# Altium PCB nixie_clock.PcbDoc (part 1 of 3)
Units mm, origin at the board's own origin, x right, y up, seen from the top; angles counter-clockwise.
Board outline 295 x 120 mm, 2 copper layers (Top Layer, Bottom Layer), stack 0.325 mm thick; 320 components, 396 nets, 1330 pads, 452 vias.
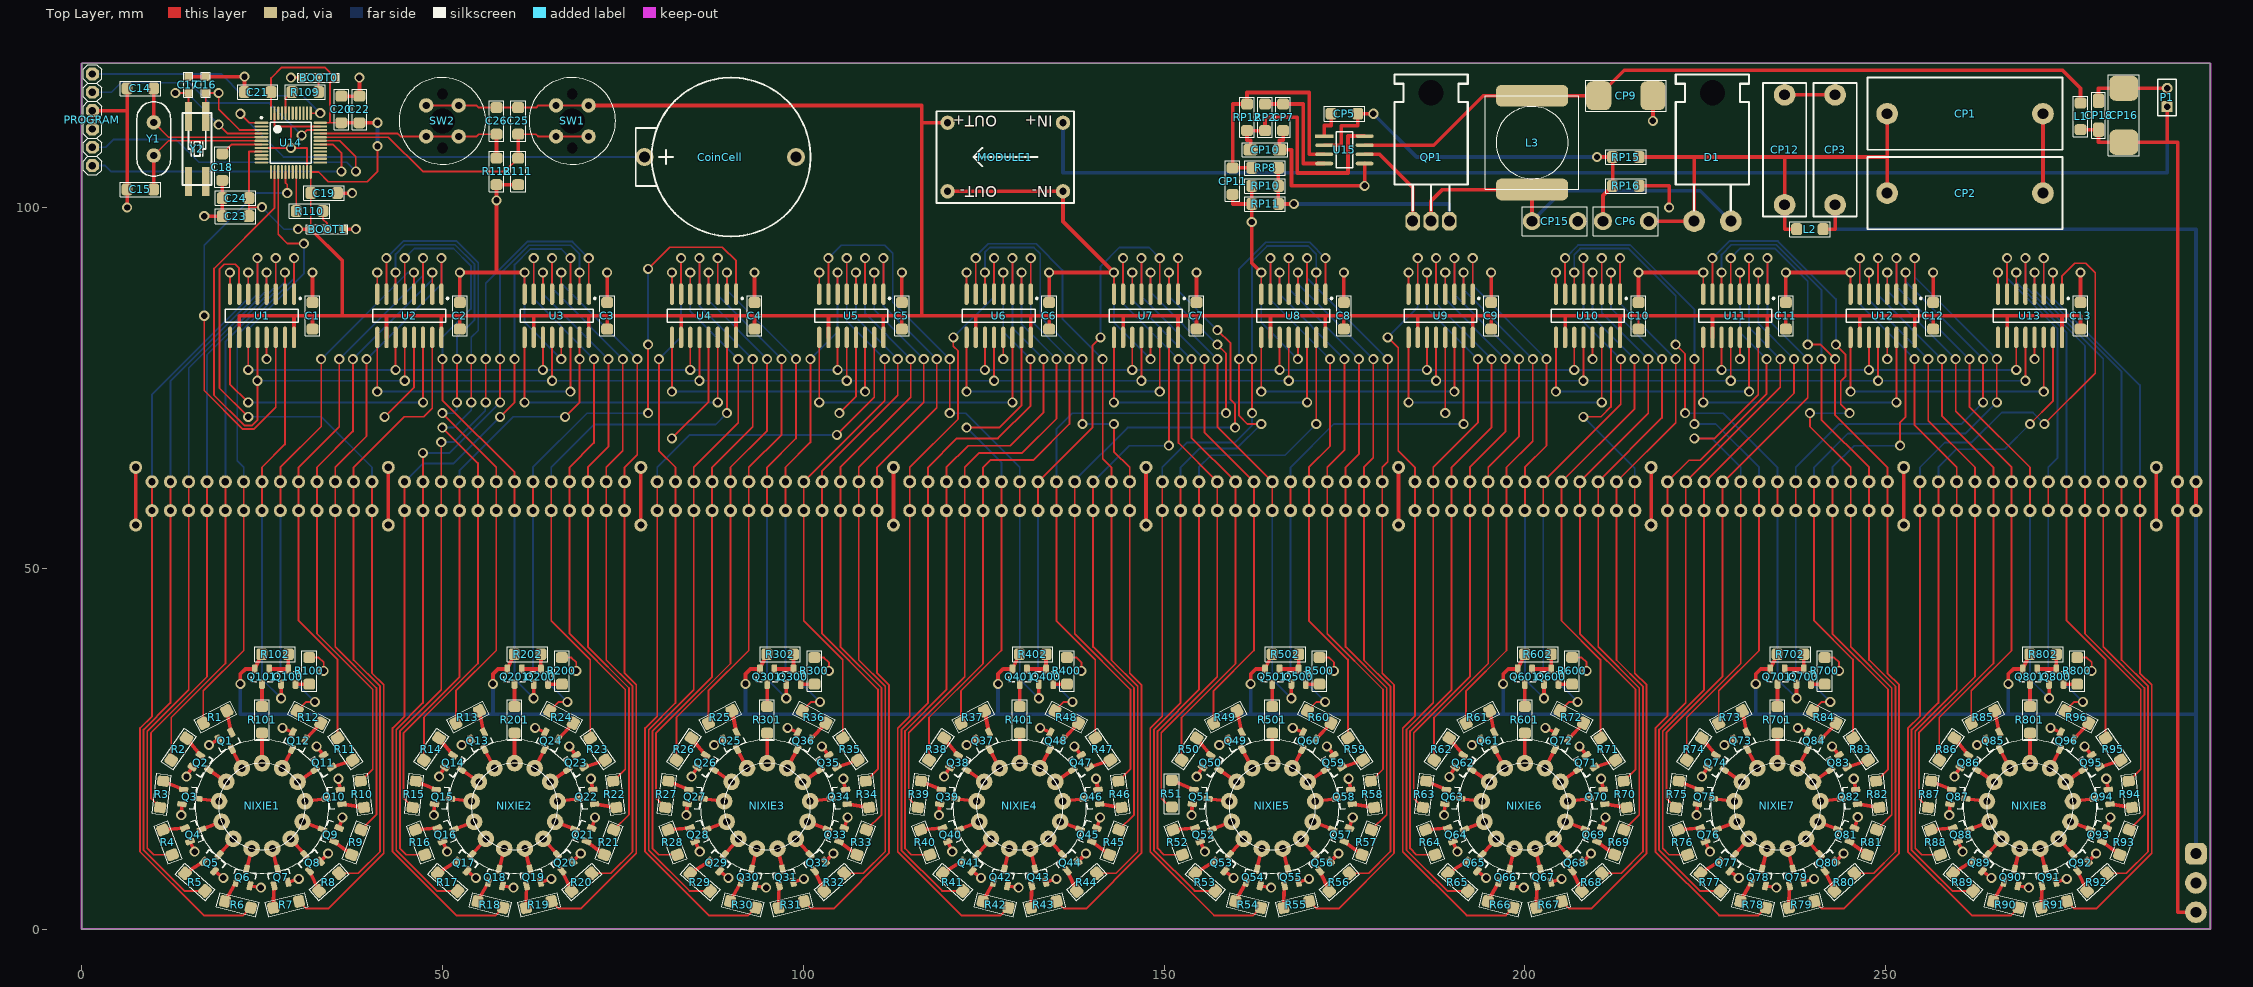
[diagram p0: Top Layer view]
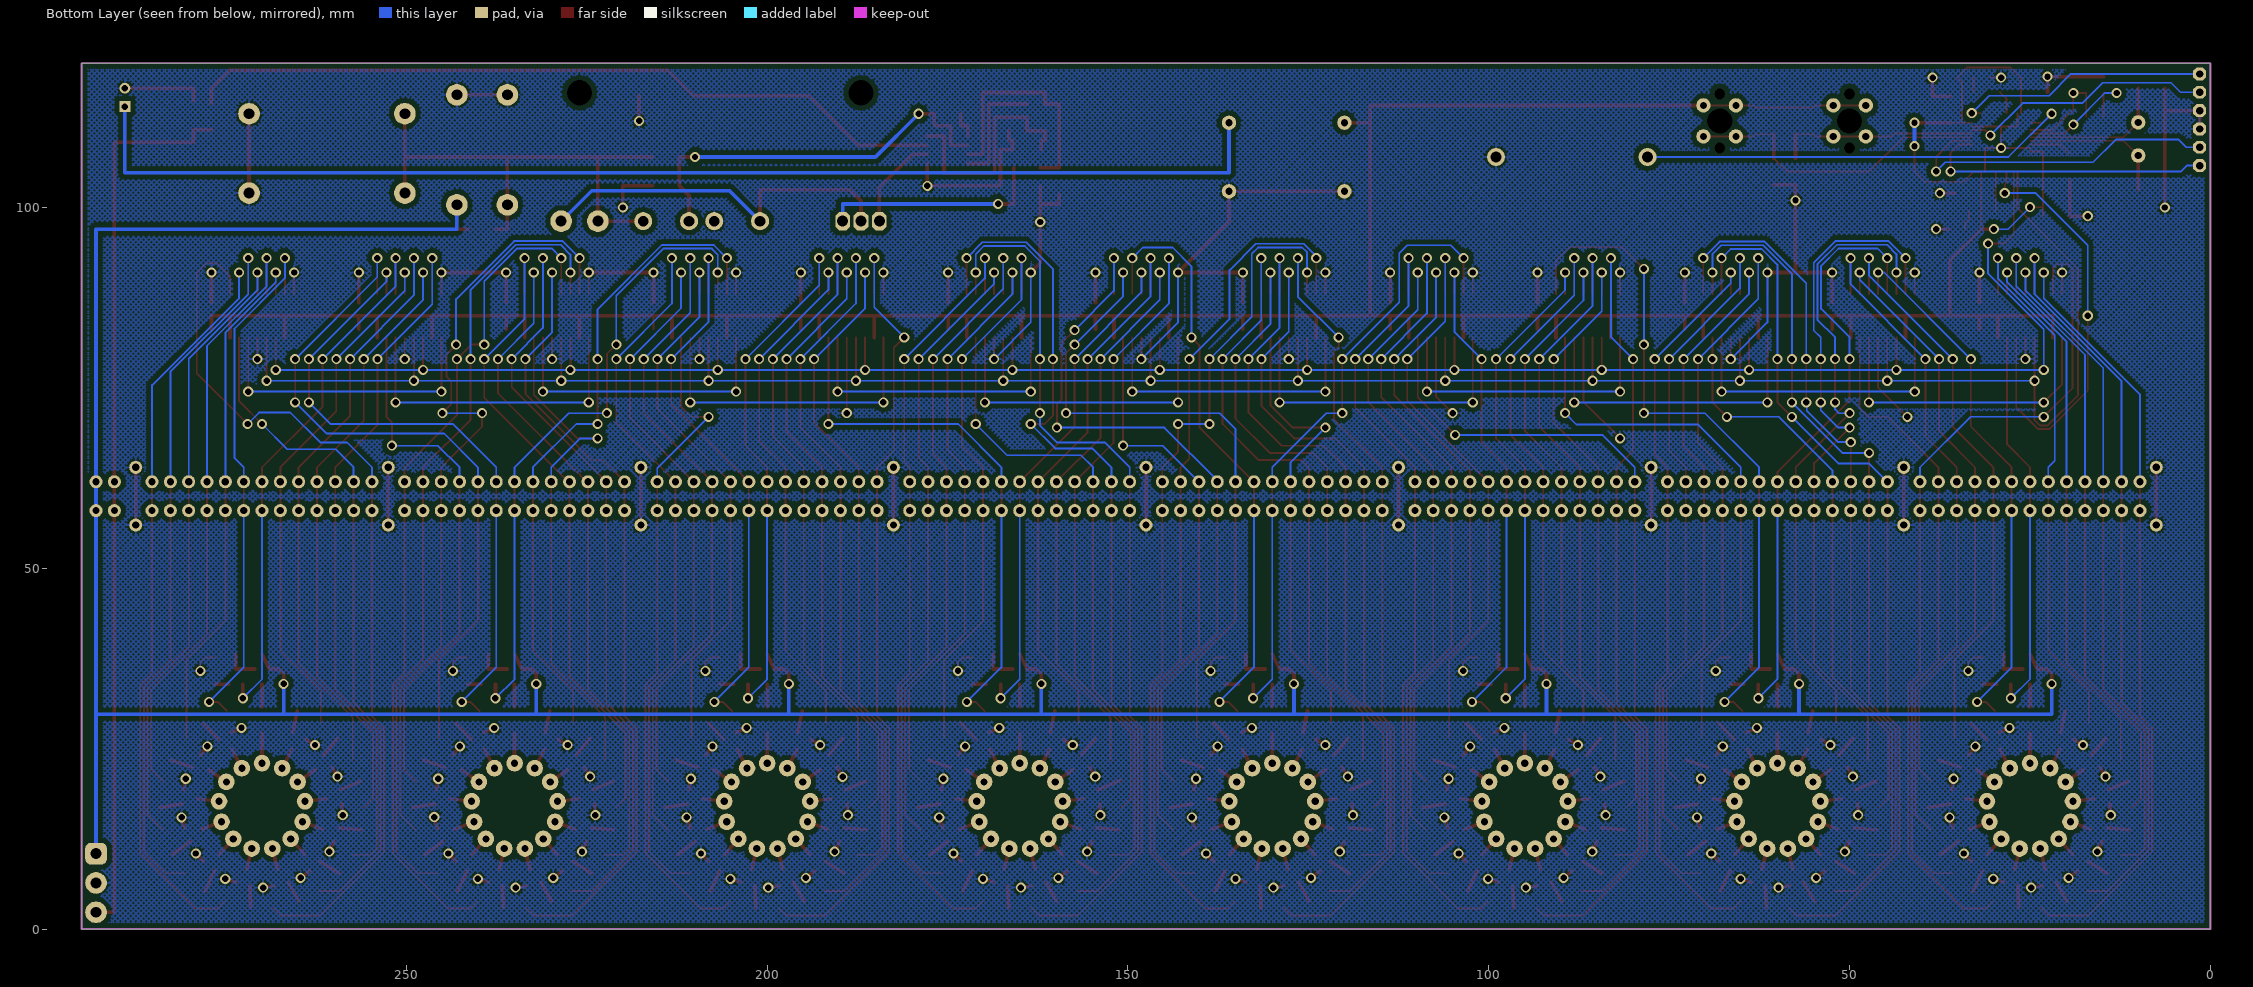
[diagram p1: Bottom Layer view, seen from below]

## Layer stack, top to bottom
Top Solder: solder mask 0.0102, Solder Resist, Dk 3.5
Top Layer: signal copper 0.0356
Dielectric 1: core 0.254, FR-4, Dk 4.2
Bottom Layer: signal copper 0.0356
Bottom Solder: solder mask 0.0102, Solder Resist, Dk 3.5

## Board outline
0,0 0,120 295,120 295,0

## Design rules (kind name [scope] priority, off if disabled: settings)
Clearance [All] p1: gap=0.635
PolygonConnect [All] p1: connectstyle=Relief reliefconductorwidth=0.254 reliefentries=4 polygonreliefangle="90 Angle" airgapwidth=0.254
RoutingVias [All] p1: holewidth=0.889 width=1.397 viastyle="Through Hole" minholewidth=0.889 minwidth=1.397 maxholewidth=0.889 maxwidth=1.397
SolderMaskExpansion [All] p1: expansion=0.102
Width [All] p1: maxlimit=0.508 minlimit=0.254 preferedwidth=0.508
30 further rules are at their usual default settings.

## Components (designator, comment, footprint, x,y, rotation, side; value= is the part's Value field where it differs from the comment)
BOOT0 "Header 3" SMDJ 33.97,118 r180 top
BOOT1 "Header 3" SMDJ 32.89,97 r0 top
C1 "CAP" SMD[1206] 32,85 r270 top
C2 "CAP" SMD[1206] 52.417,85 r270 top
C3 "CAP" SMD[1206] 72.833,85 r270 top
C4 "CAP" SMD[1206] 93.25,85 r270 top
C5 "CAP" SMD[1206] 113.667,85 r270 top
C6 "CAP" SMD[1206] 134.083,85 r270 top
C7 "CAP" SMD[1206] 154.5,85 r270 top
C8 "CAP" SMD[1206] 174.917,85 r270 top
C9 "CAP" SMD[1206] 195.333,85 r270 top
C10 "CAP" SMD[1206] 215.75,85 r270 top
C11 "CAP" SMD[1206] 236.167,85 r270 top
C12 "CAP" SMD[1206] 256.583,85 r270 top
C13 "CAP" SMD[1206] 277,85 r270 top
C14 "Cap" SMD[1206] 8.15,116.5 r0 top
C15 "Cap" SMD[1206] 8.15,102.5 r0 top
C16 "Cap" SMD[0805] 17.2,117 r270 top
C17 "Cap" SMD[0805] 14.8,117 r270 top
C18 "CAP" SMD[1206] 19.5,105.6 r90 top
C19 "CAP" SMD[1206] 33.6,102 r180 top
C20 "CAP" SMD[1206] 36,113.59 r270 top
C21 "CAP" SMD[1206] 24.41,116 r0 top
C22 "CAP" SMD[1206] 38.5,113.59 r270 top
C23 "CAP" SMD[1206] 21.34,98.8 r0 top
C24 "CAP" SMD[1206] 21.34,101.3 r0 top
C25 "CAP" SMD[1206] 60.5,112 r90 top
C26 "CAP" SMD[1206] 57.5,112 r90 top
CoinCell "Header 2" COINCELL[CR2032] 90,107 r180 top
CP1 "Cap Semi" MKT27X10 261,113 r0 top
CP2 "Cap Semi" MKT27X10 261,102 r0 top
CP3 "Cap Semi" MKT18X6 243,108 r90 top
CP5 "Cap Semi" SMD[1206] 175,113 r0 top
CP6 "Cap Semi" CAP[SEC] 214,98.11 r180 top
CP7 "Cap Semi" SMD[1206] 166.5,112.5 r270 top
CP9 "Cap Semi" SMDCAP[D] 214,115.5 r0 top
CP10 "Cap Semi" SMDCAP[A] 164,108 r0 top
CP11 "Cap Semi" SMD[1206] 159.5,103.66 r270 top
CP12 "Cap Semi" MKT18X6 236,108 r90 top
CP15 "Cap Semi" CAP[SEC] 204.16,98.11 r0 top
CP16 "Cap Semi" SMDCAP[D] 283,112.79 r90 top
CP18 "Cap Semi" SMDCAP[A] 279.5,112.79 r90 top
D1 "Diode" TO-220H-2PIN 226,107 r0 top
L1 "Inductor" SMD[1206] 277,112.63 r270 top
L2 "Inductor" SMD[1206] 239.5,97 r180 top
L3 "Inductor" POWERINDUCTOR 201,109 r90 top
MODULE1 "TINY_STEPDOWN" TINY_STEPDOWN 128,107 r180 top
NIXIE1 "IN14_NIXIE_TUBE" IN14_NIXIE_TUBE 25,17 r0 top
NIXIE2 "IN14_NIXIE_TUBE" IN14_NIXIE_TUBE 60,17 r0 top
NIXIE3 "IN14_NIXIE_TUBE" IN14_NIXIE_TUBE 95,17 r0 top
NIXIE4 "IN14_NIXIE_TUBE" IN14_NIXIE_TUBE 130,17 r0 top
NIXIE5 "IN14_NIXIE_TUBE" IN14_NIXIE_TUBE 165,17 r0 top
NIXIE6 "IN14_NIXIE_TUBE" IN14_NIXIE_TUBE 200,17 r0 top
NIXIE7 "IN14_NIXIE_TUBE" IN14_NIXIE_TUBE 235,17 r0 top
NIXIE8 "IN14_NIXIE_TUBE" IN14_NIXIE_TUBE 270,17 r0 top
P1 "Header 2" HDR1X2 289,114 r90 top
PROGRAM "Header 6" H1X06F 1.49,112.16 r270 top
Q1 "MMBTA42" SOT23(TO236) 20.353,25.855 r297.69 top
Q2 "MMBTA42" SOT23(TO236) 16.77,22.681 r325.38 top
Q3 "MMBTA42" SOT23(TO236) 15.073,18.206 r353.08 top
Q4 "MMBTA42" SOT23(TO236) 15.65,13.454 r20.77 top
Q5 "MMBTA42" SOT23(TO236) 18.369,9.515 r48.46 top
Q6 "MMBTA42" SOT23(TO236) 22.607,7.291 r76.15 top
Q7 "MMBTA42" SOT23(TO236) 27.393,7.29 r103.84 top
Q8 "MMBTA42" SOT23(TO236) 31.631,9.515 r131.54 top
Q9 "MMBTA42" SOT23(TO236) 34.35,13.453 r159.23 top
Q10 "MMBTA42" SOT23(TO236) 34.927,18.205 r186.92 top
Q11 "MMBTA42" SOT23(TO236) 33.23,22.68 r214.61 top
Q12 "MMBTA42" SOT23(TO236) 29.648,25.854 r242.3 top
Q13 "MMBTA42" SOT23(TO236) 55.353,25.855 r297.69 top
Q14 "MMBTA42" SOT23(TO236) 51.77,22.681 r325.38 top
Q15 "MMBTA42" SOT23(TO236) 50.073,18.206 r353.08 top
Q16 "MMBTA42" SOT23(TO236) 50.65,13.454 r20.77 top
Q17 "MMBTA42" SOT23(TO236) 53.369,9.515 r48.46 top
Q18 "MMBTA42" SOT23(TO236) 57.607,7.291 r76.15 top
Q19 "MMBTA42" SOT23(TO236) 62.393,7.29 r103.84 top
Q20 "MMBTA42" SOT23(TO236) 66.631,9.515 r131.54 top
Q21 "MMBTA42" SOT23(TO236) 69.35,13.453 r159.23 top
Q22 "MMBTA42" SOT23(TO236) 69.927,18.205 r186.92 top
Q23 "MMBTA42" SOT23(TO236) 68.23,22.68 r214.61 top
Q24 "MMBTA42" SOT23(TO236) 64.648,25.854 r242.3 top
Q25 "MMBTA42" SOT23(TO236) 90.353,25.855 r297.69 top
Q26 "MMBTA42" SOT23(TO236) 86.77,22.681 r325.38 top
Q27 "MMBTA42" SOT23(TO236) 85.073,18.206 r353.08 top
Q28 "MMBTA42" SOT23(TO236) 85.65,13.454 r20.77 top
Q29 "MMBTA42" SOT23(TO236) 88.369,9.515 r48.46 top
Q30 "MMBTA42" SOT23(TO236) 92.607,7.291 r76.15 top
Q31 "MMBTA42" SOT23(TO236) 97.393,7.29 r103.84 top
Q32 "MMBTA42" SOT23(TO236) 101.631,9.515 r131.54 top
Q33 "MMBTA42" SOT23(TO236) 104.35,13.453 r159.23 top
Q34 "MMBTA42" SOT23(TO236) 104.927,18.205 r186.92 top
Q35 "MMBTA42" SOT23(TO236) 103.23,22.68 r214.61 top
Q36 "MMBTA42" SOT23(TO236) 99.648,25.854 r242.3 top
Q37 "MMBTA42" SOT23(TO236) 125.353,25.855 r297.69 top
Q38 "MMBTA42" SOT23(TO236) 121.77,22.681 r325.38 top
Q39 "MMBTA42" SOT23(TO236) 120.073,18.206 r353.08 top
Q40 "MMBTA42" SOT23(TO236) 120.65,13.454 r20.77 top
Q41 "MMBTA42" SOT23(TO236) 123.369,9.515 r48.46 top
Q42 "MMBTA42" SOT23(TO236) 127.607,7.291 r76.15 top
Q43 "MMBTA42" SOT23(TO236) 132.393,7.29 r103.84 top
Q44 "MMBTA42" SOT23(TO236) 136.631,9.515 r131.54 top
Q45 "MMBTA42" SOT23(TO236) 139.35,13.453 r159.23 top
Q46 "MMBTA42" SOT23(TO236) 139.927,18.205 r186.92 top
Q47 "MMBTA42" SOT23(TO236) 138.23,22.68 r214.61 top
Q48 "MMBTA42" SOT23(TO236) 134.648,25.854 r242.3 top
Q49 "MMBTA42" SOT23(TO236) 160.353,25.855 r297.69 top
Q50 "MMBTA42" SOT23(TO236) 156.77,22.681 r325.38 top
Q51 "MMBTA42" SOT23(TO236) 155.073,18.206 r353.08 top
Q52 "MMBTA42" SOT23(TO236) 155.65,13.454 r20.77 top
Q53 "MMBTA42" SOT23(TO236) 158.369,9.515 r48.46 top
Q54 "MMBTA42" SOT23(TO236) 162.607,7.291 r76.15 top
Q55 "MMBTA42" SOT23(TO236) 167.393,7.29 r103.84 top
Q56 "MMBTA42" SOT23(TO236) 171.631,9.515 r131.54 top
Q57 "MMBTA42" SOT23(TO236) 174.35,13.453 r159.23 top
Q58 "MMBTA42" SOT23(TO236) 174.927,18.205 r186.92 top
Q59 "MMBTA42" SOT23(TO236) 173.23,22.68 r214.61 top
Q60 "MMBTA42" SOT23(TO236) 169.648,25.854 r242.3 top
Q61 "MMBTA42" SOT23(TO236) 195.353,25.855 r297.69 top
Q62 "MMBTA42" SOT23(TO236) 191.77,22.681 r325.38 top
Q63 "MMBTA42" SOT23(TO236) 190.073,18.206 r353.08 top
Q64 "MMBTA42" SOT23(TO236) 190.65,13.454 r20.77 top
Q65 "MMBTA42" SOT23(TO236) 193.369,9.515 r48.46 top
Q66 "MMBTA42" SOT23(TO236) 197.607,7.291 r76.15 top
Q67 "MMBTA42" SOT23(TO236) 202.393,7.29 r103.84 top
Q68 "MMBTA42" SOT23(TO236) 206.631,9.515 r131.54 top
Q69 "MMBTA42" SOT23(TO236) 209.35,13.453 r159.23 top
Q70 "MMBTA42" SOT23(TO236) 209.927,18.205 r186.92 top
Q71 "MMBTA42" SOT23(TO236) 208.23,22.68 r214.61 top
Q72 "MMBTA42" SOT23(TO236) 204.648,25.854 r242.3 top
Q73 "MMBTA42" SOT23(TO236) 230.353,25.855 r297.69 top
Q74 "MMBTA42" SOT23(TO236) 226.77,22.681 r325.38 top
Q75 "MMBTA42" SOT23(TO236) 225.073,18.206 r353.08 top
Q76 "MMBTA42" SOT23(TO236) 225.65,13.454 r20.77 top
Q77 "MMBTA42" SOT23(TO236) 228.369,9.515 r48.46 top
Q78 "MMBTA42" SOT23(TO236) 232.607,7.291 r76.15 top
Q79 "MMBTA42" SOT23(TO236) 237.393,7.29 r103.84 top
Q80 "MMBTA42" SOT23(TO236) 241.631,9.515 r131.54 top
Q81 "MMBTA42" SOT23(TO236) 244.35,13.453 r159.23 top
Q82 "MMBTA42" SOT23(TO236) 244.927,18.205 r186.92 top
Q83 "MMBTA42" SOT23(TO236) 243.23,22.68 r214.61 top
Q84 "MMBTA42" SOT23(TO236) 239.648,25.854 r242.3 top
Q85 "MMBTA42" SOT23(TO236) 265.353,25.855 r297.69 top
Q86 "MMBTA42" SOT23(TO236) 261.77,22.681 r325.38 top
Q87 "MMBTA42" SOT23(TO236) 260.073,18.206 r353.08 top
Q88 "MMBTA42" SOT23(TO236) 260.65,13.454 r20.77 top
Q89 "MMBTA42" SOT23(TO236) 263.369,9.515 r48.46 top
Q90 "MMBTA42" SOT23(TO236) 267.607,7.291 r76.15 top
Q91 "MMBTA42" SOT23(TO236) 272.393,7.29 r103.84 top
Q92 "MMBTA42" SOT23(TO236) 276.631,9.515 r131.54 top
Q93 "MMBTA42" SOT23(TO236) 279.35,13.453 r159.23 top
Q94 "MMBTA42" SOT23(TO236) 279.927,18.205 r186.92 top
Q95 "MMBTA42" SOT23(TO236) 278.23,22.68 r214.61 top
Q96 "MMBTA42" SOT23(TO236) 274.648,25.854 r242.3 top
Q100 "MMBTA42" SOT23(TO236) 28.65,35 r90 top
Q101 "MMBTA92" SOT23(TO236) 25,35 r270 top
Q200 "MMBTA42" SOT23(TO236) 63.65,35 r90 top
Q201 "MMBTA92" SOT23(TO236) 60,35 r270 top
Q300 "MMBTA42" SOT23(TO236) 98.65,35 r90 top
Q301 "MMBTA92" SOT23(TO236) 95,35 r270 top
Q400 "MMBTA42" SOT23(TO236) 133.65,35 r90 top
Q401 "MMBTA92" SOT23(TO236) 130,35 r270 top
Q500 "MMBTA42" SOT23(TO236) 168.65,35 r90 top
Q501 "MMBTA92" SOT23(TO236) 165,35 r270 top
Q600 "MMBTA42" SOT23(TO236) 203.65,35 r90 top
Q601 "MMBTA92" SOT23(TO236) 200,35 r270 top
Q700 "MMBTA42" SOT23(TO236) 238.65,35 r90 top
Q701 "MMBTA92" SOT23(TO236) 235,35 r270 top
Q800 "MMBTA42" SOT23(TO236) 273.65,35 r90 top
Q801 "MMBTA92" SOT23(TO236) 270,35 r270 top
QP1 "IRFB4229" TO-220H 187,107 r0 top
R1 "RES" SMD[1206] 18.494,29.396 r207.69 top
R2 "RES" SMD[1206] 13.478,24.953 r235.38 top
R3 "RES" SMD[1206] 11.102,18.688 r263.08 top
R4 "RES" SMD[1206] 11.91,12.036 r290.77 top
R5 "RES" SMD[1206] 15.716,6.521 r318.46 top
R6 "RES" SMD[1206] 21.649,3.407 r346.15 top
R7 "RES" SMD[1206] 28.35,3.407 r13.84 top
R8 "RES" SMD[1206] 34.283,6.52 r41.54 top
R9 "RES" SMD[1206] 38.09,12.035 r69.23 top
R10 "RES" SMD[1206] 38.898,18.687 r96.92 top
R11 "RES" SMD[1206] 36.522,24.952 r124.61 top
R12 "RES" SMD[1206] 31.507,29.396 r152.3 top
R13 "RES" SMD[1206] 53.494,29.396 r207.49 top
R14 "RES" SMD[1206] 48.478,24.953 r235.38 top
R15 "RES" SMD[1206] 46.102,18.688 r263.08 top
R16 "RES" SMD[1206] 46.91,12.036 r290.77 top
R17 "RES" SMD[1206] 50.716,6.521 r318.46 top
R18 "RES" SMD[1206] 56.649,3.407 r346.15 top
R19 "RES" SMD[1206] 63.35,3.407 r13.84 top
R20 "RES" SMD[1206] 69.283,6.52 r41.54 top
R21 "RES" SMD[1206] 73.09,12.035 r69.23 top
R22 "RES" SMD[1206] 73.898,18.687 r96.92 top
R23 "RES" SMD[1206] 71.522,24.952 r124.61 top
R24 "RES" SMD[1206] 66.507,29.396 r152.3 top
R25 "RES" SMD[1206] 88.494,29.396 r207.69 top
R26 "RES" SMD[1206] 83.478,24.953 r235.38 top
R27 "RES" SMD[1206] 81.102,18.688 r263.08 top
R28 "RES" SMD[1206] 81.91,12.036 r290.77 top
R29 "RES" SMD[1206] 85.716,6.521 r318.46 top
R30 "RES" SMD[1206] 91.649,3.407 r346.15 top
R31 "RES" SMD[1206] 98.35,3.407 r13.84 top
R32 "RES" SMD[1206] 104.283,6.52 r41.54 top
R33 "RES" SMD[1206] 108.09,12.035 r69.23 top
R34 "RES" SMD[1206] 108.898,18.687 r96.92 top
R35 "RES" SMD[1206] 106.522,24.952 r124.61 top
R36 "RES" SMD[1206] 101.507,29.396 r152.3 top
R37 "RES" SMD[1206] 123.494,29.396 r207.69 top
R38 "RES" SMD[1206] 118.478,24.953 r235.38 top
R39 "RES" SMD[1206] 116.102,18.688 r263.08 top
R40 "RES" SMD[1206] 116.91,12.036 r290.77 top
R41 "RES" SMD[1206] 120.716,6.521 r318.46 top
R42 "RES" SMD[1206] 126.649,3.407 r346.15 top
R43 "RES" SMD[1206] 133.35,3.407 r13.84 top
R44 "RES" SMD[1206] 139.283,6.52 r41.54 top
R45 "RES" SMD[1206] 143.09,12.035 r69.23 top
R46 "RES" SMD[1206] 143.898,18.687 r96.92 top
R47 "RES" SMD[1206] 141.522,24.952 r124.61 top
R48 "RES" SMD[1206] 136.507,29.396 r152.3 top
R49 "RES" SMD[1206] 158.494,29.396 r207.69 top
R50 "RES" SMD[1206] 153.478,24.953 r235.38 top
R51 "RES" SMD[1206] 151.075,18.775 r270 top
R52 "RES" SMD[1206] 151.91,12.036 r290.77 top
R53 "RES" SMD[1206] 155.716,6.521 r318.46 top
R54 "RES" SMD[1206] 161.649,3.407 r346.15 top
R55 "RES" SMD[1206] 168.35,3.407 r13.84 top
R56 "RES" SMD[1206] 174.283,6.52 r41.54 top
R57 "RES" SMD[1206] 178.09,12.035 r69.23 top
R58 "RES" SMD[1206] 178.898,18.687 r96.92 top
R59 "RES" SMD[1206] 176.522,24.952 r124.61 top
R60 "RES" SMD[1206] 171.507,29.396 r152.3 top
R61 "RES" SMD[1206] 193.494,29.396 r207.69 top
R62 "RES" SMD[1206] 188.478,24.953 r235.38 top
R63 "RES" SMD[1206] 186.102,18.688 r263.08 top
R64 "RES" SMD[1206] 186.91,12.036 r290.77 top
R65 "RES" SMD[1206] 190.716,6.521 r318.46 top
R66 "RES" SMD[1206] 196.649,3.407 r346.15 top
R67 "RES" SMD[1206] 203.35,3.407 r13.84 top
R68 "RES" SMD[1206] 209.283,6.52 r41.54 top
R69 "RES" SMD[1206] 213.09,12.035 r69.23 top
R70 "RES" SMD[1206] 213.898,18.687 r96.92 top
R71 "RES" SMD[1206] 211.522,24.952 r124.61 top
R72 "RES" SMD[1206] 206.507,29.396 r152.3 top
R73 "RES" SMD[1206] 228.494,29.396 r207.69 top
R74 "RES" SMD[1206] 223.478,24.953 r235.38 top
R75 "RES" SMD[1206] 221.102,18.688 r263.08 top
R76 "RES" SMD[1206] 221.91,12.036 r290.77 top
R77 "RES" SMD[1206] 225.716,6.521 r318.46 top
R78 "RES" SMD[1206] 231.649,3.407 r346.15 top
R79 "RES" SMD[1206] 238.35,3.407 r13.84 top
R80 "RES" SMD[1206] 244.283,6.52 r41.54 top
R81 "RES" SMD[1206] 248.09,12.035 r69.23 top
R82 "RES" SMD[1206] 248.898,18.687 r96.92 top
R83 "RES" SMD[1206] 246.522,24.952 r124.61 top
R84 "RES" SMD[1206] 241.507,29.396 r152.3 top
R85 "RES" SMD[1206] 263.494,29.396 r207.69 top
R86 "RES" SMD[1206] 258.478,24.953 r235.38 top
R87 "RES" SMD[1206] 256.102,18.688 r263.08 top
R88 "RES" SMD[1206] 256.91,12.036 r290.77 top
R89 "RES" SMD[1206] 260.716,6.521 r318.46 top
R90 "RES" SMD[1206] 266.649,3.407 r346.15 top
R91 "RES" SMD[1206] 273.35,3.407 r13.84 top
R92 "RES" SMD[1206] 279.283,6.52 r41.54 top
R93 "RES" SMD[1206] 283.09,12.035 r69.23 top
R94 "RES" SMD[1206] 283.898,18.687 r96.92 top
R95 "RES" SMD[1206] 281.522,24.952 r124.61 top
R96 "RES" SMD[1206] 276.507,29.396 r152.3 top
R100 "RES" SMD[1206] 31.55,35.795 r90 top
R101 "RES" SMD[1206] 25,29 r270 top
R102 "RES" SMD[1206] 26.81,38.1 r0 top
R109 "RES" SMD[1206] 31,116 r180 top
R110 "RES" SMD[1206] 31.59,99.5 r0 top
R111 "RES" SMD[1206] 60.5,105 r90 top
R112 "RES" SMD[1206] 57.5,105 r90 top
R200 "RES" SMD[1206] 66.55,35.795 r90 top
R201 "RES" SMD[1206] 60,29 r270 top
R202 "RES" SMD[1206] 61.81,38.1 r0 top
R300 "RES" SMD[1206] 101.55,35.795 r90 top
R301 "RES" SMD[1206] 95,29 r270 top
R302 "RES" SMD[1206] 96.81,38.1 r0 top
R400 "RES" SMD[1206] 136.55,35.795 r90 top
R401 "RES" SMD[1206] 130,29 r270 top
R402 "RES" SMD[1206] 131.81,38.1 r0 top
R500 "RES" SMD[1206] 171.55,35.795 r90 top
R501 "RES" SMD[1206] 165,29 r270 top
R502 "RES" SMD[1206] 166.81,38.1 r0 top
R600 "RES" SMD[1206] 206.55,35.795 r90 top
R601 "RES" SMD[1206] 200,29 r270 top
R602 "RES" SMD[1206] 201.81,38.1 r0 top
R700 "RES" SMD[1206] 241.55,35.795 r90 top
R701 "RES" SMD[1206] 235,29 r270 top
R702 "RES" SMD[1206] 236.81,38.1 r0 top
R800 "RES" SMD[1206] 276.55,35.795 r90 top
R801 "RES" SMD[1206] 270,29 r270 top
R802 "RES" SMD[1206] 271.81,38.1 r0 top
RP2 "Res2" SMD[1206] 164,112.5 r90 top
RP8 "Res2" SMD[1206] 164,105.5 r0 top
RP10 "Res2" SMD[1206] 164,103 r180 top
RP11 "Res2" SMD[1206] 164,100.5 r180 top
RP12 "Res2" SMD[1206] 161.5,112.5 r90 top
RP15 "Res2" SMD[1206] 214,107 r180 top
RP16 "Res2" SMD[1206] 214,103 r0 top
SW1 "SW-PB" PUSHBUTTON 68,112 r0 top
SW2 "SW-PB" PUSHBUTTON 50,112 r0 top
U1 "74HC595D" SOIC16 25,85 r270 top
U2 "74HC595D" SOIC16 45.417,85 r270 top
U3 "74HC595D" SOIC16 65.833,85 r270 top
U4 "74HC595D" SOIC16 86.25,85 r270 top
U5 "74HC595D" SOIC16 106.667,85 r270 top
U6 "74HC595D" SOIC16 127.083,85 r270 top
U7 "74HC595D" SOIC16 147.5,85 r270 top
U8 "74HC595D" SOIC16 167.917,85 r270 top
U9 "74HC595D" SOIC16 188.333,85 r270 top
U10 "74HC595D" SOIC16 208.75,85 r270 top
U11 "74HC595D" SOIC16 229.167,85 r270 top
U12 "74HC595D" SOIC16 249.583,85 r270 top
U13 "74HC595D" SOIC16 270,85 r270 top
U14 "STM32F130CBT6" LQFP48 29,109 r0 top
U15 "UCC3803" SOIC8 175,108 r0 top
Y1 "XTAL" CRYSTALL 10,109.5 r90 top
Y2 "XTAL" MC406[32.768KHZ] 16,108.12 r270 top

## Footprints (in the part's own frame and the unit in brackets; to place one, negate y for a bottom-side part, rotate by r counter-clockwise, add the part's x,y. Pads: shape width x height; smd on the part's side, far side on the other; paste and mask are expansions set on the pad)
CAP[SEC] [mm]
  round 2.5 hole 1.5: 1(-3.175,0) 2(3.175,0)
  silkscreen extent -4.5,-2 4.5,2
COINCELL[CR2032] [mm]
  round 2.5 hole 1.5: 1(-9,0) 2(12,0)
  silkscreen extent -11,-11 13.2,11
CRYSTALL [mm]
  round 2 hole 1: 1(-2.293,0) 2(2.293,0)
  silkscreen extent -5.16,-2.32 5.16,2.32
H1X06F [mil]
  oct 70x70 hole 40: 1(-250,0) 2(-150,0) 3(-50,0) 4(50,0) 5(150,0) 6(250,0)
  silkscreen extent -300,-50 300,50
HDR1X2 [mm] "Connector; Header; 2 Position"
  rect 1.5x1.5 hole 0.9: 1(0,0)
  round 1.5 hole 0.9: 2(2.54,0)
  silkscreen extent -1.27,-1.27 3.81,1.27
IN14_NIXIE_TUBE [mm]
  round 2.3 hole 1: 0(4.938,3.408) 1(-4.938,3.408) 2(-5.956,0.723) 3(-5.61,-2.128) 4(-3.979,-4.491) 5(-1.436,-5.826) 6(1.436,-5.826) 7(3.979,-4.491) 8(5.61,-2.128) 9(5.956,0.723) A(0,6) LP(-2.788,5.313) RP(2.789,5.313)
  silkscreen extent -9.25,-9.25 9.25,9.25
LQFP48 [mm] "TSQFP, 48-Leads, Body 9.0x9.0mm (max), Pitch 0.50mm, IPC Medium Density"
  oval 1.905x0.3 smd: 1(-4.075,2.75) 2(-4.075,2.25) 3(-4.075,1.75) 4(-4.075,1.25) 5(-4.075,0.75) 6(-4.075,0.25) 7(-4.075,-0.25) 8(-4.075,-0.75) 9(-4.075,-1.25) 10(-4.075,-1.75) 11(-4.075,-2.25) 12(-4.075,-2.75) 25(4.075,-2.75) 26(4.075,-2.25) 27(4.075,-1.75) 28(4.075,-1.25) 29(4.075,-0.75) 30(4.075,-0.25) 31(4.075,0.25) 32(4.075,0.75) 33(4.075,1.25) 34(4.075,1.75) 35(4.075,2.25) 36(4.075,2.75)
  oval 0.3x1.905 smd: 13(-2.75,-4.075) 14(-2.25,-4.075) 15(-1.75,-4.075) 16(-1.25,-4.075) 17(-0.75,-4.075) 18(-0.25,-4.075) 19(0.25,-4.075) 20(0.75,-4.075) 21(1.25,-4.075) 22(1.75,-4.075) 23(2.25,-4.075) 24(2.75,-4.075) 37(2.75,4.075) 38(2.25,4.075) 39(1.75,4.075) 40(1.25,4.075) 41(0.75,4.075) 42(0.25,4.075) 43(-0.25,4.075) 44(-0.75,4.075) 45(-1.25,4.075) 46(-1.75,4.075) 47(-2.25,4.075) 48(-2.75,4.075)
  silkscreen extent -4.2,-2.85 2.85,3.57, body extent -3.5,-3.5 3.5,3.5, height 1.6
MC406[32.768KHZ] [mm]
  rect 4x1 smd: 1(-4.5,1.2) 2(-4.5,-1.2) ""(4.5,-1.2) ""(4.5,1.2)
  silkscreen extent -5,-2 5,2
MKT18X6 [mm]
  round 3 hole 1.5: 1(-7.62,0) 2(7.62,0)
  silkscreen extent -9.26,-3 9.26,3
MKT27X10 [mm]
  round 3 hole 1.5: 1(-10.795,0) 2(10.795,0)
  silkscreen extent -13.5,-5 13.5,5
POWERINDUCTOR [mm]
  rrect50% 3x10 smd: 1(-6.5,0) 2(6.5,0)
  silkscreen extent -6.5,-6.5 6.5,6.5
PUSHBUTTON [mm]
  round 0 hole 1.5: 0(0,-3.75) 0(0,3.75)
  round 0 hole 3.5: 0(0,0)
  round 2 hole 1: 1(-2.25,2.15) 1(2.25,2.15) 2(-2.25,-2.15) 2(2.25,-2.15)
  silkscreen extent -6,-6 6,6
SMD[0805] [mm]
  rrect50% 1.125x1.125 smd: 1(-1.13,0) 2(1.13,0)
  silkscreen extent -1.75,-0.62 1.75,0.62
SMD[1206] [mil]
  rrect50% 60x65 smd: 1(-72.5,0) 2(72.5,0)
  silkscreen extent -110,-40 110,40
SMDCAP[A] [mm]
  rrect50% 2x1.6 smd: 1(-2,0) 2(2,0)
  silkscreen extent -3.16,-0.95 3.16,0.95
SMDCAP[D] [mm]
  rrect50% 3.5x4 smd: 1(-3.75,0) 2(3.75,0)
  silkscreen extent -5.59,-2.16 5.59,2.16
SMDJ [mm]
  rrect50% 1.125x1.125 smd: 1(-1.13,0) 2(1.13,0) 3(3.39,0)
  silkscreen extent -1.75,-0.62 4,0.62
SOIC8 [mm]
  rect 2.5x0.5 smd: 1(-2.8,1.905)
  oval 2.5x0.5 smd: 2(-2.8,0.635) 3(-2.8,-0.635) 4(-2.8,-1.905) 5(2.8,-1.905) 6(2.8,-0.635) 7(2.8,0.635) 8(2.8,1.905)
  silkscreen extent -1.15,-2.5 1.15,2.5
SOIC16 [mm] "SOIC, 16-Leads, Body 8.8x4.0mm (max), Pitch 1.27mm, IPC Medium Density"
  oval 3x0.6 smd: 1(-3,4.445) 2(-3,3.175) 3(-3,1.905) 4(-3,0.635) 5(-3,-0.635) 6(-3,-1.905) 7(-3,-3.175) 8(-3,-4.445) 9(3,-4.445) 10(3,-3.175) 11(3,-1.905) 12(3,-0.635) 13(3,0.635) 14(3,1.905) 15(3,3.175) 16(3,4.445)
  silkscreen extent -2.52,-5.08 0.9,5.42, body extent -2,-5.08 2,5.01, height 1.75
SOT23(TO236) [mm] "SOT23, 3-Leads, Body 3.0x2.6mm (max), Pitch 1.14mm, IPC Medium Density"
  rrect50% 1.3x0.8 smd: 1(-1.05,1) 2(-1.05,-1) 3(1.05,0)
  silkscreen extent 0,-1.5 0.7,1.5, body extent -0.7,-1.52 0.7,1.52, height 1.11
TINY_STEPDOWN [mm]
  round 2 hole 1: 1(-8,4.75) 2(-8,-4.75) 3(8,-4.75) 4(8,4.75)
  silkscreen extent -9.53,-6.35 9.53,6.35
TO-220H [mil]
  oct 0x0 hole 137.8: 0(-0.01,349.99)
  oct 80x100 hole 60: 1(-100,-349.99) 2(0,-349.99) 3(100,-349.99)
  silkscreen extent -200,-290 200,450
TO-220H-2PIN [mm]
  round 0 hole 3.5: 0(0,8.89)
  round 3 hole 1.524: 1(2.54,-8.89) 2(-2.54,-8.89)
  silkscreen extent -5.08,-7.37 5.08,11.43

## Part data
BOOT0 BOOT1: "Header, 3-Pin"
C1 C2 C3 C4 C5 C6 C7 C8 C9 C10 C11 C12 C13 C18 C19 C20 C21 C22 C23 C24 C25 C26 QP1 U1 U2 U3 U4 U5 U6 U7 U8 U9 U10 U11 U12 U13: "Imported"
C14 C15 C16 C17: "Capacitor"
CoinCell P1: "Header, 2-Pin"
CP1 CP2 CP3 CP5 CP6 CP7 CP9 CP10 CP11 CP12 CP15 CP16 CP18: "Capacitor (Semiconductor SIM Model)"
D1: "Default Diode"
MODULE1: "STEPDOWN MODULE"
PROGRAM: "Header, 6-Pin"
Q1 Q2 Q3 Q4 Q5 Q6 Q7 Q8 Q9 Q10 Q11 Q12 Q13 Q14 Q15 Q16 Q17 Q18 Q19 Q20 Q21 Q22 Q23 Q24 Q25 Q26 Q27 Q28 Q29 Q30 Q31 Q32 Q33 Q34 Q35 Q36 Q37 Q38 Q39 Q40 Q41 Q42 Q43 Q44 Q45 Q46 Q47 Q48 Q49 Q50 Q51 Q52 Q53 Q54 Q55 Q56 Q57 Q58 Q59 Q60 Q61 Q62 Q63 Q64 Q65 Q66 Q67 Q68 Q69 Q70 Q71 Q72 Q73 Q74 Q75 Q76 Q77 Q78 Q79 Q80 Q81 Q82 Q83 Q84 Q85 Q86 Q87 Q88 Q89 Q90 Q91 Q92 Q93 Q94 Q95 Q96 Q100 Q200 Q300 Q400 Q500 Q600 Q700 Q800: "Transistor NPN High-Voltage 30V 0.5A"
Q101 Q201 Q301 Q401 Q501 Q601 Q701 Q801: "Transistor PNP High-Voltage -300V -0.5A"
R1 R2 R3 R4 R5 R6 R7 R8 R9 R10 R11 R12 R13 R14 R15 R16 R17 R18 R19 R20 R21 R22 R23 R24 R25 R26 R27 R28 R29 R30 R31 R32 R33 R34 R35 R36 R37 R38 R39 R40 R41 R42 R43 R44 R45 R46 R47 R48 R49 R50 R51 R52 R53 R54 R55 R56 R57 R58 R59 R60 R61 R62 R63 R64 R65 R66 R67 R68 R69 R70 R71 R72 R73 R74 R75 R76 R77 R78 R79 R80 R81 R82 R83 R84 R85 R86 R87 R88 R89 R90 R91 R92 R93 R94 R95 R96 R100 R101 R102 R109 R110 R111 R112 R200 R201 R202 R300 R301 R302 R400 R401 R402 R500 R501 R502 R600 R601 R602 R700 R701 R702 R800 R801 R802 RP2 RP8 RP10 RP11 RP12 RP15 RP16: "Resistor"
SW1 SW2: "Switch"
Y1 Y2: "Crystal Oscillator"

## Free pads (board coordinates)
  round 1.8 hole 1: 1(22.46,58) 1(22.46,62) 2(19.92,58) 2(19.92,62) 3(17.38,58) 3(17.38,62) 4(14.84,58) 4(14.84,62) 5(12.3,58) 5(12.3,62) 6(9.76,58) 6(9.76,62) 7(40.24,58) 7(40.24,62) 8(37.7,58) 8(37.7,62) 9(35.16,58) 9(35.16,62) 10(32.62,58) 10(32.62,62) 11(30.08,58) 11(30.08,62) 12(27.54,58) 12(27.54,62) 13(57.46,58) 13(57.46,62) 14(54.92,58) 14(54.92,62) 15(52.38,58) 15(52.38,62) 16(49.84,58) 16(49.84,62) 17(47.3,58) 17(47.3,62) 18(44.76,58) 18(44.76,62) 19(75.24,58) 19(75.24,62) 20(72.7,58) 20(72.7,62) 21(70.16,58) 21(70.16,62) 22(67.62,58) 22(67.62,62) 23(65.08,58) 23(65.08,62) 24(62.54,58) 24(62.54,62) 25(92.46,58) 25(92.46,62) 26(89.92,58) 26(89.92,62) 27(87.38,58) 27(87.38,62) 28(84.84,58) 28(84.84,62) 29(82.3,58) 29(82.3,62) 30(79.76,58) 30(79.76,62) 31(110.24,58) 31(110.24,62) 32(107.7,58) 32(107.7,62) 33(105.16,58) 33(105.16,62) 34(102.62,58) 34(102.62,62) 35(100.08,58) 35(100.08,62) 36(97.54,58) 36(97.54,62) 37(127.46,58) 37(127.46,62) 38(124.92,58) 38(124.92,62) 39(122.38,58) 39(122.38,62) 40(119.84,58) 40(119.84,62) 41(117.3,58) 41(117.3,62) 42(114.76,58) 42(114.76,62) 43(145.24,58) 43(145.24,62) 44(142.7,58) 44(142.7,62) 45(140.16,58) 45(140.16,62) 46(137.62,58) 46(137.62,62) 47(135.08,58) 47(135.08,62) 48(132.54,58) 48(132.54,62) 49(162.46,58) 49(162.46,62) 50(159.92,58) 50(159.92,62) 51(157.38,58) 51(157.38,62) 52(154.84,58) 52(154.84,62) 53(152.3,58) 53(152.3,62) 54(149.76,58) 54(149.76,62) 55(180.24,58) 55(180.24,62) 56(177.7,58) 56(177.7,62) 57(175.16,58) 57(175.16,62) 58(172.62,58) 58(172.62,62) 59(170.08,58) 59(170.08,62) 60(167.54,58) 60(167.54,62) 61(197.46,58) 61(197.46,62) 62(194.92,58) 62(194.92,62) 63(192.38,58) 63(192.38,62) 64(189.84,58) 64(189.84,62) 65(187.3,58) 65(187.3,62) 66(184.76,58) 66(184.76,62) 67(215.24,58) 67(215.24,62) 68(212.7,58) 68(212.7,62) 69(210.16,58) 69(210.16,62) 70(207.62,58) 70(207.62,62) 71(205.08,58) 71(205.08,62) 72(202.54,58) 72(202.54,62) 73(232.46,58) 73(232.46,62) 74(229.92,58) 74(229.92,62) 75(227.38,58) 75(227.38,62) 76(224.84,58) 76(224.84,62) 77(222.3,58) 77(222.3,62) 78(219.76,58) 78(219.76,62) 79(250.24,58) 79(250.24,62) 80(247.7,58) 80(247.7,62) 81(245.16,58) 81(245.16,62) 82(242.62,58) 82(242.62,62) 83(240.08,58) 83(240.08,62) 84(237.54,58) 84(237.54,62) 85(267.46,58) 85(267.46,62) 86(264.92,58) 86(264.92,62) 87(262.38,58) 87(262.38,62) 88(259.84,58) 88(259.84,62) 89(257.3,58) 89(257.3,62) 90(254.76,58) 90(254.76,62) 91(285.24,58) 91(285.24,62) 92(282.7,58) 92(282.7,62) 93(280.16,58) 93(280.16,62) 94(277.62,58) 94(277.62,62) 95(275.08,58) 95(275.08,62) 96(272.54,58) 96(272.54,62) 100(25,58) 100(25,62) 200(60,58) 200(60,62) 300(95,58) 300(95,62) 400(130,58) 400(130,62) 500(165,58) 500(165,62) 600(200,58) 600(200,62) 700(235,58) 700(235,62) 800(270,58) 800(270,62) 807(42.5,64) 808(252.5,64) 809(77.5,64) 810(112.5,64) 811(147.5,64) 812(182.5,64) 813(217.5,64) 814(252.5,56) 815(217.5,56) 816(182.5,56) 817(147.5,56) 818(112.5,56) 819(77.5,56) 820(42.5,56) 821(290.46,62) 822(290.46,58) 823(293,62) 824(293,58) 825(287.5,56) 826(287.5,64) 827(7.5,56) 828(7.5,64)
  round 3 hole 1.5: 801(293,2.342) 802(293,6.406)
  rrect50% 3x3 hole 1.5: 803(293,10.47)

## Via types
v1: diameter 1.397, hole 0.889, Top Layer to Bottom Layer, 452 vias

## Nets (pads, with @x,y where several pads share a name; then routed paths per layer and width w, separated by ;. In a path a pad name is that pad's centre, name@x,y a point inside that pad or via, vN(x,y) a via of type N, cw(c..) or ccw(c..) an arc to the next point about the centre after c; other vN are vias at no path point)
3V3: BOOT0.1 BOOT1.1 C1.2 C2.2 C3.2 C4.2 C5.2 C6.2 C7.2 C8.2 C9.2 C10.2 C11.2 C12.2 C13.2 C19.2 C20.2 C21.2 C22.2 C23.2 C24.2 C25.2 C26.2 MODULE1.3 SW1.1 SW2.1 U1.10 U1.16 U2.10 U2.16 U3.10 U3.16 U4.10 U4.16 U5.10 U5.16 U6.10 U6.16 U7.10 U7.16 U8.10 U8.16 U9.10 U9.16 U10.10 U10.16 U11.10 U11.16 U12.10 U12.16 U13.10 U13.16 U14.9 U14.24 U14.36 U14.48 | length 547.3
  Top Layer w0.254: C23.2@23.182,98.8 23.182,100.07 ; U14.9@24.925,107.75 23.182,107.75 C24.2@23.182,101.3 23.182,100.07 ; v1(25,100.05) 23.202,100.05 23.182,100.07 ; U14.48@26.25,113.075 26.25,115.999 C21.2@26.251,116 26.251,117.951 27.71,119.41 33.69,119.41 BOOT0.1@35.1,118 34.4,117.3 34.4,111.75 ; C19.2@31.75,102.008 U14.24@31.75,104.925 32.845,104.925 34.2,103.57 39.6,103.57 41,104.97 v1(41,108.5) ; C19.2@31.759,102 31.759,97 BOOT1.1@31.76,97 ; U14.36@33.075,111.75 34.4,111.75 ; C20.2@36,111.749 35.998,111.75 34.4,111.75 ; SW2.1@47.75,114.15 SW2.1@52.25,114.15 54.71,114.15 55.019,113.841 C26.2@57.5,113.841 C25.2@60.5,113.841 62.981,113.841 63.29,114.15 SW1.1@65.75,114.15 SW1.1@70.25,114.15 ; C10.2@215.75,83.159 215.75,84.997 ; 256.58,85 256.583,84.997 ; 266.82,85 266.825,84.995 ; 274.43,85 274.445,84.985
  Top Layer w0.508: U1.10@21.825,82 21.825,85 36.14,85 ; U1.16@29.445,82 29.445,84.985 ; v1(30,97) BOOT1.1@31.759,97 ; BOOT1.1@31.76,97 36.14,92.62 36.14,85 ; C1.2@32,83.159 32,84.997 ; C20.2@36,111.749 C22.2@38.5,111.748 v1(41,111.748) ; U2.10@42.242,82 42.242,84.995 ; U2.16@49.862,82 49.862,84.985 ; C2.2@52.417,83.159 52.417,84.997 ; U3.10@62.658,82 62.658,84.995 ; SW1.1@70.25,114.15 116.43,114.15 116.43,111.75 ; U3.16@70.278,82 70.278,84.985 ; C3.2@72.833,83.159 72.833,84.997 ; U4.10@83.075,82 83.075,84.995 ; U4.16@90.695,82 90.695,84.985 ; C4.2@93.25,83.159 93.25,84.997 ; U5.10@103.492,82 103.492,84.995 ; U5.16@111.112,82 111.112,84.985 ; C5.2@113.667,83.159 113.667,84.997 ; MODULE1.3@120,111.75 116.43,111.75 ; U6.10@123.908,82 123.908,84.995 ; U6.16@131.528,82 131.528,84.985 ; C6.2@134.083,83.159 134.083,84.997 ; U7.10@144.325,82 144.325,84.995 ; U7.16@151.945,82 151.945,84.985 ; C7.2@154.5,83.159 154.5,84.997 ; U8.10@164.742,82 164.742,84.995 ; U8.16@172.362,82 172.362,84.985 ; C8.2@174.917,83.159 174.917,84.997 ; U9.10@185.158,82 185.158,84.995 ; U9.16@192.778,82 192.778,84.985 ; C9.2@195.333,83.159 195.333,84.997 ; U10.10@205.575,82 205.575,84.995 ; U10.16@213.195,82 213.195,84.985 ; U11.10@225.992,82 225.992,84.995 ; U11.16@233.612,82 233.612,84.985 ; C11.2@236.167,83.159 236.167,84.997 ; U12.10@246.408,82 246.408,84.995 ; U12.16@254.028,82 254.028,84.985 ; C12.2@256.583,83.159 256.583,84.997 ; U13.10@266.825,82 266.825,84.995 ; U13.16@274.445,82 274.445,84.985 ; C13.2@277,83.159 277,85 274.43,85 266.82,85 256.58,85 116.43,85 ; 36.14,85 116.43,85 ; 116.43,85 116.43,111.75
  Bottom Layer w0.254: v1(25,100.05) 28.05,97 v1(30,97)
  Bottom Layer w0.508: v1(41,108.5) v1(41,111.748)
CLK: U1.11 U2.11 U3.11 U4.11 U5.11 U6.11 U7.11 U8.11 U9.11 U10.11 U11.11 U12.11 U13.11 U14.15 | length 338.4
  Top Layer w0.254: v1(23.095,77.5) U1.11@23.095,82 ; U14.15@27.25,104.925 27.25,96.28 28.53,95 v1(30.8,95) ; v1(43.512,77.5) U2.11@43.512,82 ; v1(63.928,77.5) U3.11@63.928,82 ; v1(84.345,77.5) U4.11@84.345,82 ; v1(104.762,77.5) U5.11@104.762,82 ; v1@125.178,77 U6.11@125.178,82 ; v1(145.595,77.5) U7.11@145.595,82 ; v1(166.012,77.5) U8.11@166.012,82 ; v1(186.428,77.5) U9.11@186.428,82 ; v1(206.845,77.5) U10.11@206.845,82 ; v1(227.262,77.5) U11.11@227.262,82 ; v1@247.678,77 U12.11@247.678,82 ; v1@268.095,77 U13.11@268.095,82
  Bottom Layer w0.254: v1(30.8,95) 30.8,90.852 23.095,83.147 v1(23.095,77.5) v1(43.512,77.5) v1(63.928,77.5) v1(84.345,77.5) v1(104.762,77.5) v1(125.178,77.5) v1(145.595,77.5) v1(166.012,77.5) v1(186.428,77.5) v1(206.845,77.5) v1(227.262,77.5) v1(247.678,77.5) v1(268.095,77.5)
DATA: U1.14 U14.17 | length 60.7
  Top Layer w0.254: v1(17,85) 17,74.642 22.34,69.302 23.872,69.302 26.905,72.335 U1.14@26.905,82 ; U14.17@28.25,104.925 28.25,103.44 28.5,103.19 v1(28.5,102)
  Bottom Layer w0.254: v1(17,85) 17,94.78 24.22,102 v1(28.5,102)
